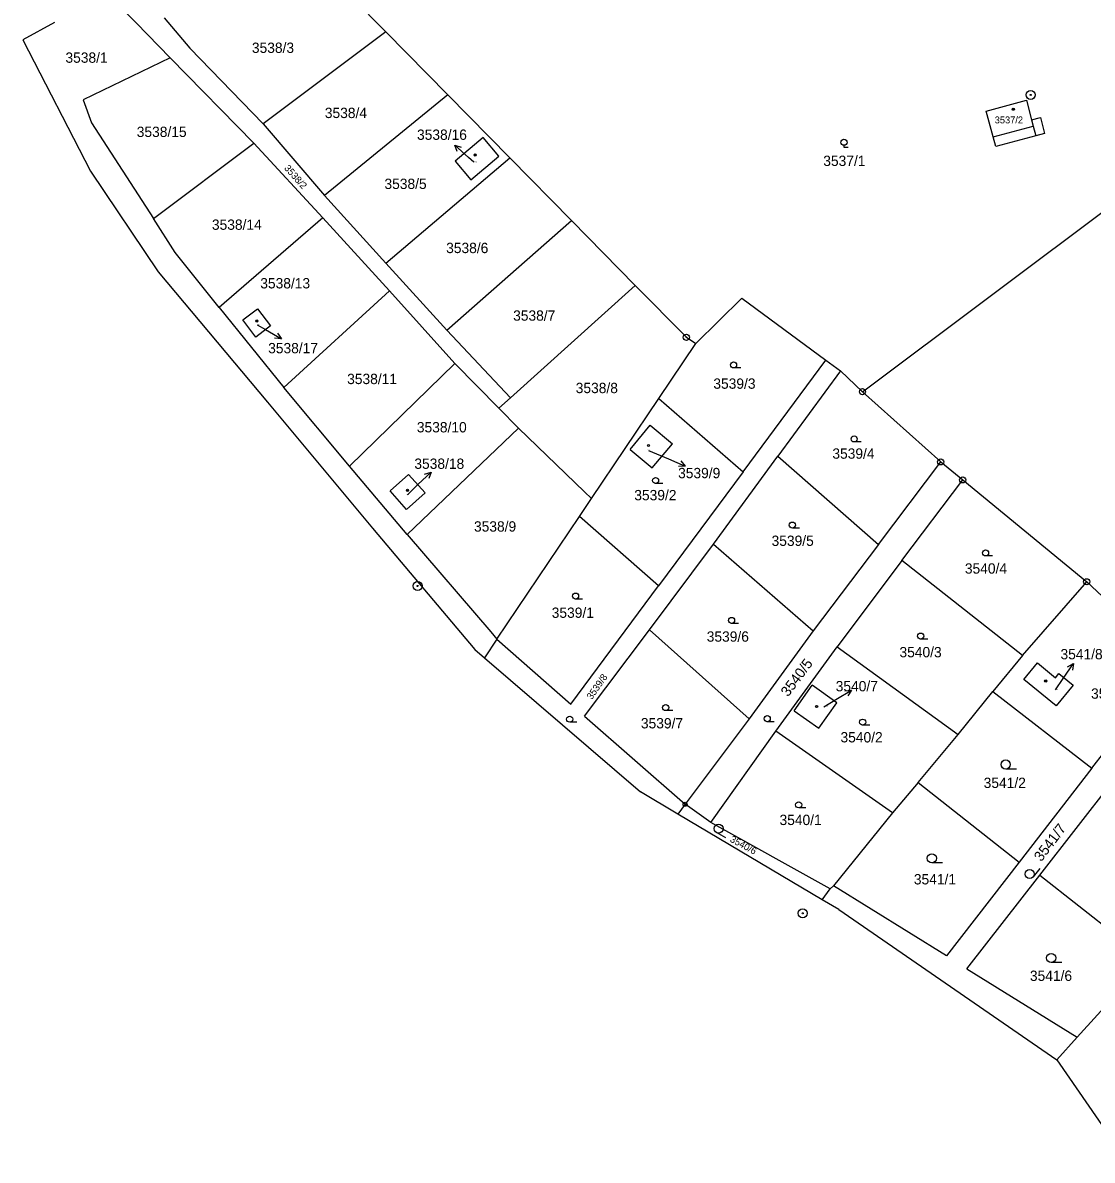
# Model space of a CAD drawing. Extents: x -593183 to -588034, y -1130415 to -1124994.
# Drawn here: x -593031.7 to -592855.4, y -1129375 to -1129187.5 of the extents above; entities that cross this region are included whole.
import ezdxf

# ---------------------------------------------------------------- set-up
doc = ezdxf.new("R2010")
doc.units = 0
for name, color, linetype in [('Vrstva 1', 7, 'Continuous'), ('Vrstva 13', 7, 'Continuous'), ('Vrstva 16', 7, 'Continuous'), ('Vrstva 18', 7, 'Continuous'), ('Vrstva 19', 7, 'Continuous'), ('Vrstva 24', 7, 'Continuous'), ('Vrstva 25', 7, 'Continuous'), ('Vrstva 4', 7, 'Continuous')]:
    doc.layers.add(name, color=color, linetype=linetype)

msp = doc.modelspace()

# ---------------------------------------------------------------- linework, layer by layer
at = {"layer": 'Vrstva 1'}
for p, q in [((-592971.9, -1129188.99), (-592979.2, -1129181.56)), ((-593014.57, -1129185.99), (-593013.05, -1129187.55)), ((-593013.05, -1129187.55), (-593007.43, -1129193.29)), ((-593008.41, -1129186.69), (-593004.18, -1129191.72)), ((-592971.9, -1129188.99), (-592992.12, -1129204.19)), ((-592971.9, -1129188.99), (-592961.65, -1129199.41)), ((-593004.18, -1129191.72), (-592992.12, -1129204.19)), ((-593007.43, -1129193.29), (-593021.76, -1129200.22)), ((-592993.64, -1129207.36), (-593007.43, -1129193.29)), ((-592961.65, -1129199.41), (-592981.98, -1129216.02)), ((-592961.65, -1129199.41), (-592951.46, -1129209.77)), ((-593021.76, -1129200.22), (-593020.4, -1129204.03)), ((-592872.91, -1129202.07), (-592866.3, -1129200.3)), ((-592866.3, -1129200.3), (-592865.45, -1129203.51)), ((-592893.32, -1129248.33), (-592831.64, -1129202.13)), ((-592871.77, -1129206.34), (-592872.91, -1129202.07)), ((-592865.45, -1129203.51), (-592865.16, -1129204.58)), ((-593020.4, -1129204.03), (-593010.2, -1129219.8)), ((-592992.12, -1129204.19), (-592981.98, -1129216.02)), ((-592865.16, -1129204.58), (-592864.75, -1129206.14)), ((-592955.85, -1129206.45), (-592960.48, -1129210.33)), ((-592953.24, -1129209.5), (-592955.85, -1129206.45)), ((-592871.36, -1129207.9), (-592871.77, -1129206.34)), ((-592864.75, -1129206.14), (-592871.36, -1129207.9)), ((-593010.2, -1129219.8), (-592993.64, -1129207.36)), ((-592993.64, -1129207.36), (-592982.29, -1129219.68)), ((-592971.9, -1129227.13), (-592951.46, -1129209.77)), ((-592960.48, -1129210.33), (-592957.86, -1129213.42)), ((-592957.86, -1129213.42), (-592953.24, -1129209.5)), ((-592951.46, -1129209.77), (-592941.29, -1129220.11)), ((-592981.98, -1129216.02), (-592971.9, -1129227.13)), ((-593006.59, -1129225.39), (-593010.2, -1129219.8)), ((-592982.29, -1129219.68), (-592999.35, -1129234.45)), ((-592982.29, -1129219.68), (-592971.29, -1129231.71)), ((-592961.85, -1129238.2), (-592941.29, -1129220.11)), ((-592941.29, -1129220.11), (-592930.77, -1129230.81)), ((-592999.35, -1129234.45), (-593006.59, -1129225.39)), ((-592971.9, -1129227.13), (-592961.85, -1129238.2)), ((-592930.77, -1129230.81), (-592951.35, -1129249.34)), ((-592922.35, -1129239.37), (-592930.77, -1129230.81)), ((-592971.29, -1129231.71), (-592988.68, -1129247.62)), ((-592971.29, -1129231.71), (-592960.53, -1129243.71)), ((-592920.78, -1129240.41), (-592913.2, -1129232.89)), ((-592913.2, -1129232.89), (-592899.35, -1129243.11)), ((-592999.35, -1129234.45), (-592988.68, -1129247.62)), ((-592995.46, -1129236.51), (-592993.04, -1129234.66)), ((-592993.04, -1129234.66), (-592990.89, -1129237.48)), ((-592993.32, -1129239.35), (-592995.46, -1129236.51)), ((-592990.89, -1129237.48), (-592993.32, -1129239.35)), ((-592961.85, -1129238.2), (-592951.35, -1129249.34)), ((-592926.87, -1129249.46), (-592920.78, -1129240.41)), ((-592922.35, -1129239.37), (-592920.78, -1129240.41)), ((-592960.53, -1129243.71), (-592977.89, -1129260.58)), ((-592960.53, -1129243.71), (-592953.24, -1129251.05)), ((-592913, -1129261.53), (-592899.35, -1129243.11)), ((-592899.35, -1129243.11), (-592896.93, -1129244.9)), ((-592896.93, -1129244.9), (-592907.25, -1129258.97)), ((-592896.93, -1129244.9), (-592893.32, -1129248.33)), ((-592977.89, -1129260.58), (-592988.68, -1129247.62)), ((-592893.32, -1129248.33), (-592880.43, -1129259.9)), ((-592951.35, -1129249.34), (-592953.24, -1129251.05)), ((-592937.98, -1129265.95), (-592926.87, -1129249.46)), ((-592926.87, -1129249.46), (-592913, -1129261.53)), ((-592953.24, -1129251.05), (-592949.99, -1129254.32)), ((-592931.63, -1129257.84), (-592928.31, -1129253.87)), ((-592928.31, -1129253.87), (-592924.65, -1129256.93)), ((-592949.99, -1129254.32), (-592968.37, -1129271.85)), ((-592949.99, -1129254.32), (-592939.11, -1129264.86)), ((-592931.63, -1129257.84), (-592927.98, -1129260.88)), ((-592927.98, -1129260.88), (-592924.65, -1129256.93)), ((-592917.9, -1129273.46), (-592907.25, -1129258.97)), ((-592907.25, -1129258.97), (-592890.65, -1129273.5)), ((-592968.37, -1129271.85), (-592977.89, -1129260.58)), ((-592913, -1129261.53), (-592926.92, -1129280.31)), ((-592890.65, -1129273.5), (-592880.43, -1129259.9)), ((-592880.43, -1129259.9), (-592876.8, -1129262.88)), ((-592886.82, -1129276.14), (-592876.8, -1129262.88)), ((-592876.8, -1129262.88), (-592856.36, -1129279.66)), ((-592937.98, -1129265.95), (-592939.11, -1129264.86)), ((-592939.97, -1129268.91), (-592937.98, -1129265.95)), ((-592953.57, -1129289.11), (-592939.97, -1129268.91)), ((-592926.92, -1129280.31), (-592939.97, -1129268.91)), ((-592968.37, -1129271.85), (-592954.6, -1129287.91)), ((-592928.43, -1129287.56), (-592917.9, -1129273.46)), ((-592917.9, -1129273.46), (-592901.45, -1129287.77)), ((-592890.65, -1129273.5), (-592901.45, -1129287.77)), ((-592886.82, -1129276.14), (-592897.48, -1129290.36)), ((-592866.93, -1129291.82), (-592886.82, -1129276.14)), ((-592941.38, -1129299.81), (-592926.92, -1129280.31)), ((-592866.93, -1129291.82), (-592856.36, -1129279.66)), ((-592856.36, -1129279.66), (-592847.38, -1129288.07)), ((-592939.12, -1129301.8), (-592928.43, -1129287.56)), ((-592928.43, -1129287.56), (-592911.98, -1129302.24)), ((-592901.45, -1129287.77), (-592911.98, -1129302.24)), ((-592953.57, -1129289.11), (-592955.64, -1129292.18)), ((-592954.6, -1129287.91), (-592953.57, -1129289.11)), ((-592953.57, -1129289.11), (-592941.38, -1129299.81)), ((-592907.58, -1129304.28), (-592897.48, -1129290.36)), ((-592897.48, -1129290.36), (-592877.54, -1129304.83)), ((-592866.93, -1129291.82), (-592871.83, -1129297.76)), ((-592866.7, -1129295.76), (-592864.48, -1129293.05)), ((-592864.48, -1129293.05), (-592861.5, -1129295.49)), ((-592861.5, -1129295.49), (-592860.93, -1129294.79)), ((-592860.93, -1129294.79), (-592858.61, -1129296.7)), ((-592904.57, -1129300.94), (-592901.62, -1129296.72)), ((-592897.55, -1129299.6), (-592901.62, -1129296.72)), ((-592861.4, -1129300.1), (-592866.7, -1129295.76)), ((-592858.61, -1129296.7), (-592861.4, -1129300.1)), ((-592877.54, -1129304.83), (-592871.83, -1129297.76)), ((-592871.83, -1129297.76), (-592855.53, -1129310.4)), ((-592904.57, -1129300.94), (-592900.52, -1129303.79)), ((-592900.52, -1129303.79), (-592897.55, -1129299.6)), ((-592939.12, -1129301.8), (-592922.56, -1129316.33)), ((-592911.98, -1129302.24), (-592922.56, -1129316.33)), ((-592855.53, -1129310.4), (-592849.45, -1129302.54)), ((-592918.3, -1129319.36), (-592907.58, -1129304.28)), ((-592888.35, -1129317.74), (-592907.58, -1129304.28)), ((-592884.13, -1129312.76), (-592877.54, -1129304.83)), ((-592855.53, -1129310.4), (-592867.51, -1129325.87)), ((-592884.13, -1129312.76), (-592888.35, -1129317.74)), ((-592884.13, -1129312.76), (-592867.51, -1129325.87)), ((-592864.09, -1129328.03), (-592852.09, -1129312.61)), ((-592922.56, -1129316.33), (-592923.75, -1129317.94)), ((-592918.3, -1129319.36), (-592922.56, -1129316.33)), ((-592888.35, -1129317.74), (-592898.08, -1129329.77)), ((-592898.67, -1129330.3), (-592918.3, -1129319.36)), ((-592867.51, -1129325.87), (-592879.49, -1129341.34)), ((-592876.09, -1129343.45), (-592864.09, -1129328.03)), ((-592864.09, -1129328.03), (-592846.37, -1129341.95)), ((-592899.97, -1129332.08), (-592898.67, -1129330.3)), ((-592898.67, -1129330.3), (-592898.08, -1129329.77)), ((-592879.49, -1129341.34), (-592898.08, -1129329.77)), ((-592846.37, -1129341.95), (-592857.95, -1129354.74)), ((-592876.09, -1129343.45), (-592857.95, -1129354.74)), ((-592857.95, -1129354.74), (-592861.31, -1129358.45))]:
    msp.add_line(p, q, dxfattribs=at)
msp.add_lwpolyline([(-592971.15, -1129264.69), (-592968.13, -1129261.98), (-592965.42, -1129265.01), (-592968.46, -1129267.76), (-592971.15, -1129264.69)], dxfattribs=at)
at = {"layer": 'Vrstva 13'}
for p, q in [((-593026.5, -1129187.49), (-593031.73, -1129190.36)), ((-593031.73, -1129190.36), (-593020.56, -1129211.97)), ((-593020.56, -1129211.97), (-593009.4, -1129228.58)), ((-593009.4, -1129228.58), (-592991.41, -1129250.07)), ((-592991.41, -1129250.07), (-592974.06, -1129270.83)), ((-592974.06, -1129270.83), (-592957.23, -1129290.82)), ((-592957.23, -1129290.82), (-592955.64, -1129292.18)), ((-592955.64, -1129292.18), (-592929.92, -1129314.28)), ((-592923.75, -1129317.94), (-592929.92, -1129314.28)), ((-592899.97, -1129332.08), (-592923.75, -1129317.94)), ((-592897.24, -1129333.69), (-592899.97, -1129332.08)), ((-592897.24, -1129333.69), (-592861.31, -1129358.45)), ((-592861.31, -1129358.45), (-592849.87, -1129375.01))]:
    msp.add_line(p, q, dxfattribs=at)
at = {"layer": 'Vrstva 16'}
for p, q in [((-592957.38, -1129210.52), (-592958.28, -1129209.71)), ((-592993.11, -1129237.29), (-592991.7, -1129238.1)), ((-592928.6, -1129258), (-592925.31, -1129259.41)), ((-592968.33, -1129265.31), (-592966.6, -1129263.64)), ((-592861.49, -1129297.48), (-592860.24, -1129295.62)), ((-592899.71, -1129300.26), (-592897.71, -1129299.07))]:
    msp.add_line(p, q, dxfattribs=at)
at = {"layer": 'Vrstva 24'}
for centre, radius in [((-592865.59, -1129199.41), 0.75), ((-592865.59, -1129199.41), 0.0903), ((-592922.35, -1129239.37), 0.5), ((-592922.35, -1129239.37), 0.0327), ((-592893.32, -1129248.33), 0.5), ((-592893.32, -1129248.33), 0.0327), ((-592880.43, -1129259.9), 0.5), ((-592880.43, -1129259.9), 0.0327), ((-592876.8, -1129262.88), 0.5), ((-592876.8, -1129262.88), 0.0327), ((-592966.65, -1129280.35), 0.75), ((-592966.65, -1129280.35), 0.0903), ((-592856.36, -1129279.66), 0.5), ((-592856.36, -1129279.66), 0.0327), ((-592922.56, -1129316.33), 0.335), ((-592922.56, -1129316.33), 0.0219), ((-592903.16, -1129334.31), 0.75), ((-592903.16, -1129334.31), 0.0903)]:
    msp.add_circle(centre, radius, dxfattribs=at)
at = {"layer": 'Vrstva 25'}
for p, q in [((-592958.28, -1129209.71), (-592960.52, -1129207.71)), ((-592896.37, -1129207.72), (-592896.37, -1129208.05)), ((-592896.37, -1129208.05), (-592895.68, -1129208.05)), ((-592991.7, -1129238.1), (-592989.1, -1129239.6)), ((-592913.39, -1129244.42), (-592914.56, -1129244.42)), ((-592893.52, -1129256.62), (-592894.69, -1129256.62)), ((-592925.31, -1129259.41), (-592922.55, -1129260.59)), ((-592966.6, -1129263.64), (-592964.43, -1129261.57)), ((-592926.25, -1129263.47), (-592927.42, -1129263.47)), ((-592903.71, -1129270.82), (-592904.88, -1129270.82)), ((-592871.86, -1129275.4), (-592873.03, -1129275.4)), ((-592939.44, -1129282.52), (-592940.61, -1129282.52)), ((-592913.73, -1129286.53), (-592914.9, -1129286.53)), ((-592882.56, -1129289.11), (-592883.73, -1129289.11)), ((-592860.24, -1129295.62), (-592858.56, -1129293.13)), ((-592897.71, -1129299.07), (-592895.13, -1129297.54)), ((-592924.58, -1129300.9), (-592925.75, -1129300.9)), ((-592940.41, -1129302.81), (-592941.58, -1129302.81)), ((-592907.85, -1129302.73), (-592909.02, -1129302.73)), ((-592892.12, -1129303.3), (-592893.29, -1129303.3)), ((-592867.95, -1129310.53), (-592869.7, -1129310.53)), ((-592902.66, -1129316.93), (-592903.83, -1129316.93)), ((-592915.86, -1129321.85), (-592917.4, -1129321.01)), ((-592880.14, -1129325.98), (-592881.89, -1129325.98)), ((-592864.1, -1129326.9), (-592865.16, -1129328.29)), ((-592860.47, -1129342.41), (-592862.22, -1129342.41))]:
    msp.add_line(p, q, dxfattribs=at)
for points in [[(-592960.1, -1129208.75), (-592960.52, -1129207.71), (-592959.44, -1129208)], [(-592989.72, -1129238.67), (-592989.1, -1129239.6), (-592990.22, -1129239.53)], [(-592923.27, -1129259.74), (-592922.55, -1129260.59), (-592923.67, -1129260.66)], [(-592965.5, -1129261.9), (-592964.43, -1129261.57), (-592964.81, -1129262.62)], [(-592859.54, -1129293.68), (-592858.56, -1129293.13), (-592858.71, -1129294.24)], [(-592896.24, -1129297.62), (-592895.13, -1129297.54), (-592895.73, -1129298.48)]]:
    msp.add_lwpolyline(points, dxfattribs=at)
for centre, radius in [((-592868.46, -1129201.78), 0.175), ((-592868.46, -1129201.78), 0.15), ((-592896.37, -1129207.21), 0.502), ((-592957.17, -1129209.31), 0.175), ((-592957.17, -1129209.31), 0.15), ((-592993.15, -1129236.68), 0.175), ((-592993.15, -1129236.68), 0.15), ((-592914.56, -1129243.92), 0.503), ((-592894.69, -1129256.12), 0.503), ((-592928.6, -1129257.21), 0.175), ((-592928.6, -1129257.21), 0.15), ((-592927.42, -1129262.97), 0.503), ((-592968.31, -1129264.59), 0.175), ((-592968.31, -1129264.59), 0.15), ((-592904.88, -1129270.32), 0.503), ((-592873.03, -1129274.9), 0.503), ((-592940.61, -1129282.02), 0.503), ((-592914.9, -1129286.03), 0.503), ((-592883.73, -1129288.61), 0.503), ((-592863.12, -1129296.02), 0.175), ((-592863.12, -1129296.02), 0.15), ((-592925.75, -1129300.4), 0.503), ((-592900.87, -1129300.22), 0.175), ((-592900.87, -1129300.22), 0.15), ((-592941.58, -1129302.31), 0.503), ((-592909.02, -1129302.23), 0.503), ((-592893.29, -1129302.8), 0.503), ((-592869.7, -1129309.78), 0.75), ((-592903.83, -1129316.43), 0.503), ((-592917.04, -1129320.35), 0.75), ((-592881.89, -1129325.23), 0.75), ((-592865.76, -1129327.84), 0.75), ((-592862.22, -1129341.66), 0.75)]:
    msp.add_circle(centre, radius, dxfattribs=at)
at = {"layer": 'Vrstva 4'}
for p, q in [((-592865.45, -1129203.51), (-592863.99, -1129203.12)), ((-592863.99, -1129203.12), (-592863.29, -1129205.75)), ((-592871.77, -1129206.34), (-592865.16, -1129204.58)), ((-592863.29, -1129205.75), (-592864.75, -1129206.14))]:
    msp.add_line(p, q, dxfattribs=at)

# ---------------------------------------------------------------- texts
at = {"layer": 'Vrstva 16'}
for s, p in [('3538/16', (-592966.74, -1129206.82)), ('3538/17', (-592991.28, -1129242)), ('3538/18', (-592967.18, -1129261.05)), ('3539/9', (-592923.71, -1129262.59)), ('3541/8', (-592860.68, -1129292.44)), ('3540/7', (-592897.73, -1129297.72))]:
    msp.add_text(s, height=1.7, dxfattribs=at).set_placement(p)
at = {"layer": 'Vrstva 18'}
for s, p in [('3538/3', (-592993.96, -1129192.49)), ('3538/1', (-593024.69, -1129194.12)), ('3538/4', (-592981.94, -1129203.23)), ('3538/15', (-593012.94, -1129206.35)), ('3537/1', (-592899.78, -1129211.13)), ('3538/5', (-592972.11, -1129214.92)), ('3538/14', (-593000.55, -1129221.65)), ('3538/6', (-592961.94, -1129225.49)), ('3538/13', (-592992.58, -1129231.31)), ('3538/7', (-592950.9, -1129236.63)), ('3538/11', (-592978.26, -1129247.08)), ('3539/3', (-592917.9, -1129247.85)), ('3538/8', (-592940.58, -1129248.57)), ('3538/10', (-592966.77, -1129255.04)), ('3539/4', (-592898.28, -1129259.38)), ('3539/2', (-592930.93, -1129266.23)), ('3538/9', (-592957.35, -1129271.39)), ('3539/5', (-592908.3, -1129273.75)), ('3540/4', (-592876.44, -1129278.32)), ('3539/1', (-592944.54, -1129285.61)), ('3539/6', (-592918.99, -1129289.54)), ('3540/3', (-592887.22, -1129292.11)), ('3541/3', (-592855.64, -1129298.94)), ('3539/7', (-592929.84, -1129303.83)), ('3540/2', (-592896.94, -1129306.14)), ('3541/2', (-592873.34, -1129313.65)), ('3540/1', (-592906.99, -1129319.76)), ('3541/1', (-592884.85, -1129329.55)), ('3541/6', (-592865.72, -1129345.45))]:
    msp.add_text(s, height=1.7, dxfattribs=at).set_placement(p)
for s, height, rotation, p in [('3538/2', 1.14, 311.6094, (-592988.72, -1129211.54)), ('3540/5', 1.7, 53.2619, (-592905.57, -1129298.72)), ('3539/8', 1.14, 55.1721, (-592937.94, -1129299.18)), ('3541/7', 1.7, 52.7908, (-592863.85, -1129325.9)), ('3540/6', 1.14, 331.4812, (-592915.26, -1129322.44))]:
    msp.add_text(s, height=height, rotation=rotation, dxfattribs=at).set_placement(p)
at = {"layer": 'Vrstva 19'}
for s, height, p in [('3537/2', 1.14, (-592871.52, -1129204.11)), ('3538/16', 0.1, (-592957.38, -1129210.52)), ('3538/17', 0.1, (-592993.11, -1129237.29)), ('3539/9', 0.1, (-592928.83, -1129258)), ('3538/18', 0.1, (-592968.58, -1129265.31)), ('3541/8', 0.1, (-592861.49, -1129297.48)), ('3540/7', 0.2, (-592899.71, -1129300.26))]:
    msp.add_text(s, height=height, dxfattribs=at).set_placement(p)

doc.saveas('drawing.dxf')
